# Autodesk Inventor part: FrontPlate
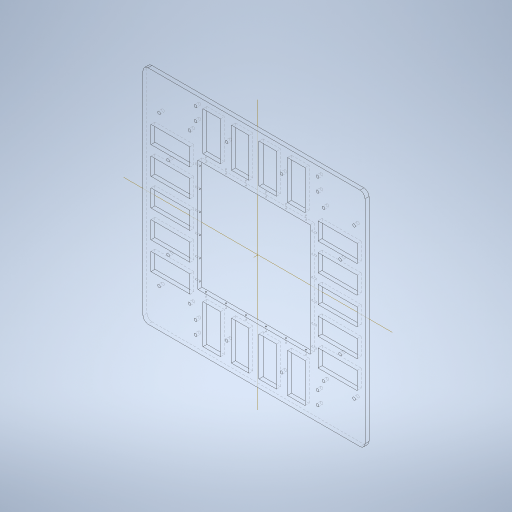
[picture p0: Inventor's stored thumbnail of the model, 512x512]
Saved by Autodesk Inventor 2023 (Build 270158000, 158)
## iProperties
Created: 2023-10
Part Number: FrontPlate
Material: Aluminum 7075
Document SubType Name: Modeling
Designer: tornqvih
Density: 2.81 g/cm^3
Appearance: Satin - Brushed Heavy
Mass: 3290.29 g
Surface Area: 3180.89 cm^2
Volume: 1170.92 cm^3
Author: tornqvih
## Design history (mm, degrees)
sketch "Sketch1" dims "d4" = 8
  geometry: L1 (-212, 222)-(212, 222); L2 (222, 212)-(222, -212); L3 (212, -222)-(-212, -222); L4 (-222, -212)-(-222, 212); L5 (-222, 222)-(222, -222); L6 (222, 222)-(-222, -222); L7 (0, -313.699)-(0, 313.699) reference; L8 (-313.699, 0)-(313.699, 0) reference; A1 r 10 centre (-212, 212) between (-212, 222) and (-222, 212); A2 r 10 centre (212, 212) between (222, 212) and (212, 222); A3 r 10 centre (-212, -212) between (-222, -212) and (-212, -222); A4 r 10 centre (212, -212) between (212, -222) and (222, -212)
  constraints: 12 end point, 8 point on circle, 8 point on line, 8 tangent, 4 centre point, 2 parallel, 1 horizontal, 1 perpendicular, 2 other
  dimensions: "d0" = 444 distance of L5.start L6.start; "d1" = 444 distance of L6.end L5.start; "d10" = 10 radius of A1 (derived); "d11" = 10 radius of A2 (derived); "d12" = 10 radius of A3 (derived); "d13" = 10 radius of A4 (derived)
extrude "Extrusion1" new body sketch "Sketch1" distance "d4" = 8; taper "d5" = 0 deg
sketch "Sketch2"
  geometry: L1 (-112, -112)-(112, -112); L2 (112, -112)-(112, 112); L3 (112, 112)-(-112, 112); L4 (-112, 112)-(-112, -112); L5 (-112, -112)-(112, 112); L6 (112, -112)-(-112, 112); L7 (-102, 206)-(-67, 206); L8 (-67, 206)-(-67, 128); L9 (-67, 128)-(-102, 128); L10 (-102, 128)-(-102, 206); L11 (212, 222)-(-212, 222) reference; L12 (-45, 206)-(-10, 206); L13 (-10, 206)-(-10, 128); L14 (-10, 128)-(-45, 128); L15 (-45, 128)-(-45, 206); L16 (0, -310.8)-(0, 310.8) reference; L17 (10, 206)-(45, 206); L18 (45, 206)-(45, 128); L19 (45, 128)-(10, 128); L20 (10, 128)-(10, 206); L21 (67, 206)-(102, 206); L22 (102, 206)-(102, 128); L23 (102, 128)-(67, 128); L24 (67, 128)-(67, 206); L25 (-102, -128)-(-67, -128); L26 (-67, -128)-(-67, -206); L27 (-67, -206)-(-102, -206); L28 (-102, -206)-(-102, -128); L29 (-45, -128)-(-10, -128); L30 (-10, -128)-(-10, -206); L31 (-10, -206)-(-45, -206); L32 (-45, -206)-(-45, -128); L33 (10, -128)-(45, -128); L34 (45, -128)-(45, -206); L35 (45, -206)-(10, -206); L36 (10, -206)-(10, -128); L37 (67, -128)-(102, -128); L38 (102, -128)-(102, -206); L39 (102, -206)-(67, -206); L40 (67, -206)-(67, -128); L41 (-310.8, 0)-(310.8, 0) reference; L42 (-206, 127)-(-128, 127); L43 (-128, 127)-(-128, 92); L44 (-128, 92)-(-206, 92); L45 (-206, 92)-(-206, 127); L46 (-206, 72)-(-128, 72); L47 (-128, 72)-(-128, 37); L48 (-128, 37)-(-206, 37); L49 (-206, 37)-(-206, 72); L50 (-206, 17)-(-128, 17); L51 (-128, 17)-(-128, -18); L52 (-128, -18)-(-206, -18); L53 (-206, -18)-(-206, 17); L54 (-206, -38)-(-128, -38); L55 (-128, -38)-(-128, -73); L56 (-128, -73)-(-206, -73); L57 (-206, -73)-(-206, -38); L58 (-206, -93)-(-128, -93); L59 (-128, -93)-(-128, -128); L60 (-128, -128)-(-206, -128); L61 (-206, -128)-(-206, -93); L62 (-222, 212)-(-222, -212) reference; L63 (128, 127)-(206, 127); L64 (206, 127)-(206, 92)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; 1 further point
  constraints: 156 end point, 44 symmetric about line, 18 point on line, 16 parallel, 8 horizontal, 8 perpendicular, 8 vertical alignment, 2 horizontal alignment, 2 midpoint
  dimensions: "d6" = 224 distance of L2.end L3.end; "d7" = 224 distance of L3.end L1.start; "d79" = 10 distance between parallel lines of L4 L10; "d80" = 35 distance between parallel lines of L8 L10; "d81" = 16 distance between parallel lines of L11 L7; "d82" = 16 distance between parallel lines of L3 L9; "d83" = 35 distance between parallel lines of L13 L15; "d84" = 10 distance between parallel lines of L16 L13; "d85" = 16 distance between parallel lines of L4 L43; "d86" = 16 distance between parallel lines of L62 L45; "d87" = 35 distance between parallel lines of L44 L42; "d88" = 15 distance between parallel lines of L3 L42; "d89" = 35 distance between parallel lines of L48 L46; "d90" = 35 distance between parallel lines of L52 L50; "d91" = 35 distance between parallel lines of L56 L54; "d92" = 35 distance between parallel lines of L60 L58; "d93" = 20 distance between parallel lines of L46 L44; "d94" = 20 distance between parallel lines of L50 L48; "d95" = 20 distance between parallel lines of L54 L52; "d96" = 20 distance between parallel lines of L58 L56
extrude "Extrusion2" cut sketch "Sketch2" distance "d8" = 8; taper "d9" = 0 deg
sketch "Sketch3"
  geometry: L1 (-222, 212)-(-222, -212) reference; L2 (212, 222)-(-212, 222) reference; L3 (0, -310.8)-(0, 310.8) reference; L4 (-310.8, 0)-(310.8, 0) reference; L5 (-112, -112)-(-112, 112) reference; L6 (-212, -222)-(212, -222) reference; L7 (112, 112)-(112, -112) reference; L8 (222, -212)-(222, 212) reference; L9 (112, -112)-(-112, -112) reference; 28 further points
  constraints: 10 horizontal alignment, 10 vertical alignment, 6 symmetric about line, 3 coincident
  dimensions: "d23" = 67 distance from line of L2 point (-190, 155); "d24" = 19 distance from line of L2 point (-117, 203); "d26" = 17 distance from line of L5 point (-129, 155); "d64" = 26 distance of point (-117, 177) point (-117, 203); "d66" = 29 distance from line of L6 point (-117, -193); "d67" = 26 distance of point (-117, -167) point (-117, -193); "d69" = 15 distance from line of L7 point (127, 177); "d70" = 22 distance from line of L8 point (200, 155); "d71" = 61 distance of point (200, 155) point (139, 155); "d72" = 5 horizontal distance of L5.end point (-117, 203); "d73" = 61 distance of point (-129, 155) point (-190, 155); "d74" = 33 distance from line of L9 point (-190, -145); "d75" = 55 distance from line of L3 point (-55, 172); "d76" = 50 distance from line of L2 point (-55, 172); "d77" = 82 distance from line of L4 point (-172, 82); "d78" = 50 distance from line of L1 point (-172, 82)
hole "Hole1" sketch "Sketch3" diameter "d14" = 5.5; stored, may be unused: countersink angle "d18" = 90 deg, drill point angle "d20" = 118 deg; dims "d15" = 6, "d16" = 4, "d17" = 2, "d19" = 8
sketch "Sketch4"
  geometry: L1 (112, 9.6)-(112, -1.6) reference; L2 (324, 0)-(-100, 0) reference; 7 further points
  constraints: 3 symmetric about line, 2 horizontal alignment
  dimensions: "d28" = 4 distance from line of L2 point (12, 4); "d29" = 20 distance from line of L1 point (92, 4); "d30" = 60 distance from line of L1 point (52, 4); "d31" = 100 distance from line of L1 point (12, 4)
hole "Hole2" sketch "Sketch4" at (12, 4), (52, 4), (92, 4), (132, 4), (172, 4), (212, 4) diameter "d32" = 2.459; stored, may be unused: countersink angle "d36" = 90 deg, drill point angle "d38" = 118 deg; dims "d33" = 6, "d34" = 4, "d35" = 2, "d37" = 8.8
sketch "Sketch5"
  geometry: L1 (9.6, 112)-(-1.6, 112) reference; L2 (8, -100)-(8, 324) reference; 7 further points
  constraints: 3 symmetric about line, 2 vertical alignment
  dimensions: "d39" = 4 distance from line of L2 point (4, 212); "d40" = 20 distance from line of L1 point (4, 132); "d41" = 60 distance from line of L1 point (4, 172); "d42" = 100 distance from line of L1 point (4, 212)
hole "Hole3" sketch "Sketch5" at (4, 212), (4, 172), (4, 132), (4, 92), (4, 52), (4, 12) diameter "d43" = 2.459; stored, may be unused: countersink angle "d47" = 90 deg, drill point angle "d49" = 118 deg; dims "d44" = 6, "d45" = 4, "d46" = 2, "d48" = 8.8
sketch "Sketch6"
  geometry: C1 r 1.23 at (12, -4) reference; C2 r 1.23 at (52, -4) reference; C3 r 1.23 at (92, -4) reference; C4 r 1.23 at (132, -4) reference; C5 r 1.23 at (172, -4) reference; C6 r 1.23 at (212, -4) reference; 7 further points
  constraints: 6 coincident
hole "Hole4" sketch "Sketch6" at (12, -4), (52, -4), (92, -4), (132, -4), (172, -4), (212, -4) diameter "d50" = 2.459; stored, may be unused: countersink angle "d54" = 90 deg, drill point angle "d56" = 118 deg; dims "d51" = 6, "d52" = 4, "d53" = 2, "d55" = 8.8
sketch "Sketch7"
  geometry: C1 r 1.23 at (-4, 212) reference; C2 r 1.23 at (-4, 172) reference; C3 r 1.23 at (-4, 132) reference; C4 r 1.23 at (-4, 92) reference; C5 r 1.23 at (-4, 52) reference; C6 r 1.23 at (-4, 12) reference; 7 further points
  constraints: 6 coincident
hole "Hole5" sketch "Sketch7" at (-4, 212), (-4, 172), (-4, 132), (-4, 92), (-4, 52), (-4, 12) diameter "d57" = 2.459; stored, may be unused: countersink angle "d61" = 90 deg, drill point angle "d63" = 118 deg; dims "d58" = 6, "d59" = 4, "d60" = 2, "d62" = 8.8
node "FrontPlate"
